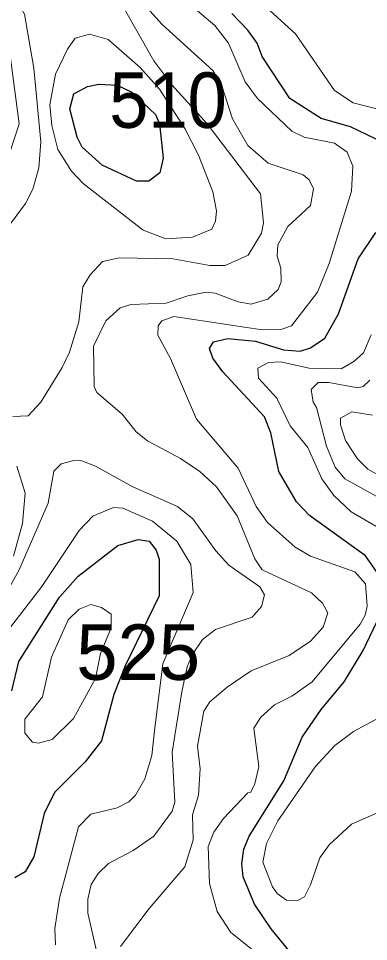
# Model space of a CAD drawing. Extents: x 673.6 to 698.9, y 7012 to 7040.1.
# Drawn here: x 682.378 to 682.883, y 7013.137 to 7014.47 of the extents above; entities that cross this region are included whole.
import ezdxf

# ---------------------------------------------------------------- set-up
doc = ezdxf.new("R2010")
doc.units = 0
doc.header["$LTSCALE"] = 0.032
doc.layers.add('1', color=7, linetype='Continuous', lineweight=25)
doc.layers.add('2', color=7, linetype='Continuous', lineweight=13)
doc.layers.add('21', color=7, linetype='Continuous')

msp = doc.modelspace()

# ---------------------------------------------------------------- linework, layer by layer
at = {"layer": '1'}
for points in [[(682.9054, 7014.29), (682.8574, 7014.3132), (682.8151, 7014.3254), (682.7698, 7014.3541), (682.73, 7014.4147), (682.7227, 7014.434), (682.7095, 7014.4529), (682.6862, 7014.477)], [(682.9052, 7013.6567), (682.8793, 7013.6939), (682.7982, 7013.7522), (682.7797, 7013.7716), (682.7541, 7013.8157), (682.7427, 7013.8711), (682.7335, 7013.8944), (682.6731, 7013.9594), (682.6588, 7013.9792), (682.6539, 7013.993), (682.66, 7014.0028), (682.6803, 7014.0075), (682.7206, 7014.0035), (682.7609, 7013.991), (682.7847, 7013.989), (682.7996, 7013.9942), (682.8203, 7014.0082), (682.8402, 7014.0429), (682.8686, 7014.1225), (682.8938, 7014.1604)], [(682.369, 7013.4986), (682.3791, 7013.5413), (682.4376, 7013.634), (682.4645, 7013.6646), (682.5219, 7013.7085), (682.5509, 7013.7173), (682.567, 7013.715), (682.5772, 7013.7017), (682.5812, 7013.689), (682.5814, 7013.6361), (682.5325, 7013.5348), (682.5162, 7013.4937), (682.4982, 7013.4265), (682.4748, 7013.3965), (682.4305, 7013.3518), (682.4155, 7013.3217), (682.4005, 7013.259), (682.3879, 7013.2373), (682.3733, 7013.2288)], [(682.7989, 7013.0867), (682.7428, 7013.155), (682.7191, 7013.1907), (682.7028, 7013.2302), (682.7006, 7013.2494), (682.7035, 7013.2702), (682.7114, 7013.2889), (682.7613, 7013.369), (682.7879, 7013.4319), (682.8153, 7013.4717), (682.8482, 7013.5119), (682.8759, 7013.5572), (682.9049, 7013.6185)]]:
    msp.add_lwpolyline(points, dxfattribs=at)
msp.add_lwpolyline([(682.5763, 7014.3308), (682.5819, 7014.3175), (682.587, 7014.2677), (682.5825, 7014.2467), (682.5665, 7014.2345), (682.5486, 7014.2349), (682.499, 7014.2576), (682.4705, 7014.2837), (682.4632, 7014.2981), (682.4524, 7014.339), (682.4585, 7014.3609), (682.4782, 7014.3716), (682.4943, 7014.3748), (682.5206, 7014.3733), (682.5419, 7014.3633)], close=True, dxfattribs=at)
at = {"layer": '2'}
for points in [[(682.5678, 7014.5395), (682.6618, 7014.4594), (682.6815, 7014.4341), (682.7056, 7014.378), (682.7232, 7014.3539), (682.773, 7014.3071), (682.7907, 7014.2981), (682.8344, 7014.2894), (682.8525, 7014.2766), (682.8606, 7014.2564), (682.8591, 7014.2203), (682.8265, 7014.1159), (682.8098, 7014.0742), (682.7724, 7014.0256), (682.757, 7014.0207), (682.7298, 7014.0199), (682.6025, 7014.0395), (682.5851, 7014.0332), (682.5799, 7014.0257), (682.5797, 7014.0124), (682.5978, 7013.9787), (682.6351, 7013.891), (682.6953, 7013.8204), (682.7212, 7013.7649), (682.7378, 7013.7417), (682.7774, 7013.7061), (682.7995, 7013.6932), (682.8637, 7013.6708), (682.8789, 7013.6534), (682.8814, 7013.6212), (682.8787, 7013.6083), (682.8712, 7013.5949), (682.802, 7013.5117), (682.7726, 7013.491), (682.7476, 7013.4787), (682.7282, 7013.4606), (682.7179, 7013.4451), (682.725, 7013.3894), (682.7195, 7013.3645), (682.7136, 7013.3525), (682.7095, 7013.3514), (682.674, 7013.3145), (682.6603, 7013.295), (682.6522, 7013.274), (682.6538, 7013.2208), (682.6652, 7013.1801), (682.6847, 7013.1498), (682.735, 7013.1101)], [(682.3636, 7014.1687), (682.3885, 7014.2026), (682.3993, 7014.2232), (682.4078, 7014.2541), (682.4105, 7014.2916), (682.4004, 7014.398), (682.387, 7014.4758), (682.3797, 7014.4884), (682.3387, 7014.5263)], [(682.5209, 7014.5021), (682.5739, 7014.4082), (682.5997, 7014.3739), (682.6506, 7014.3177), (682.7274, 7014.2163), (682.7317, 7014.1744), (682.7292, 7014.1598), (682.7097, 7014.1279), (682.6767, 7014.1128), (682.6546, 7014.1128), (682.6015, 7014.1225), (682.5235, 7014.1242), (682.4998, 7014.1189), (682.482, 7014.0995), (682.4713, 7014.0822), (682.4655, 7014.0317), (682.4518, 7013.9877), (682.4416, 7013.9656), (682.4107, 7013.9158), (682.3923, 7013.896), (682.3703, 7013.895)], [(682.5258, 7013.1296), (682.5671, 7013.1846), (682.6183, 7013.2446), (682.6306, 7013.2835), (682.6296, 7013.32), (682.6381, 7013.3484), (682.6406, 7013.3863), (682.6365, 7013.4187), (682.6458, 7013.4695), (682.6547, 7013.4827), (682.6795, 7013.504), (682.7139, 7013.5275), (682.769, 7013.55), (682.7999, 7013.5704), (682.8182, 7013.5908), (682.8247, 7013.6114), (682.817, 7013.6254), (682.8013, 7013.6404), (682.7298, 7013.6734), (682.7193, 7013.6894), (682.6941, 7013.7516), (682.664, 7013.7933), (682.6399, 7013.8153), (682.6124, 7013.8345), (682.5647, 7013.8596), (682.5483, 7013.873), (682.5279, 7013.8982), (682.4915, 7013.9296), (682.4877, 7013.9381), (682.4868, 7013.9965), (682.5045, 7014.0328), (682.5251, 7014.0517), (682.5404, 7014.0564), (682.5917, 7014.0585), (682.6227, 7014.0692), (682.6493, 7014.0742), (682.6621, 7014.0732), (682.6954, 7014.0605), (682.7142, 7014.0569), (682.7383, 7014.0644), (682.753, 7014.0785), (682.7572, 7014.0893), (682.7571, 7014.1093), (682.7515, 7014.1262), (682.7525, 7014.143), (682.7671, 7014.1694), (682.7997, 7014.1997), (682.804, 7014.2236), (682.7976, 7014.2365), (682.7891, 7014.2439), (682.7385, 7014.2609), (682.7092, 7014.2864), (682.6871, 7014.3245), (682.672, 7014.3725), (682.6586, 7014.3945), (682.5857, 7014.4609), (682.5592, 7014.4904)], [(682.9235, 7014.332), (682.8612, 7014.3476), (682.8345, 7014.3658), (682.778, 7014.4476), (682.7361, 7014.4856)], [(682.3619, 7014.4489), (682.3792, 7014.3173), (682.3665, 7014.2773)], [(682.9089, 7013.7277), (682.8584, 7013.7574), (682.8333, 7013.781), (682.816, 7013.8051), (682.796, 7013.8502), (682.7705, 7013.8815), (682.7512, 7013.9215), (682.7247, 7013.9504), (682.7237, 7013.9649), (682.7391, 7013.973), (682.7563, 7013.9739), (682.7976, 7013.9648), (682.844, 7013.9639), (682.8624, 7013.9745), (682.8761, 7013.9867), (682.8873, 7014.0127)], [(682.8852, 7013.9473), (682.8757, 7013.9384), (682.8678, 7013.9361), (682.8262, 7013.9442), (682.8109, 7013.9442), (682.8008, 7013.934), (682.8034, 7013.9158), (682.8083, 7013.9078), (682.823, 7013.8522), (682.8351, 7013.8216), (682.8491, 7013.8047), (682.9032, 7013.7751)], [(682.9032, 7013.8072), (682.8826, 7013.819), (682.8676, 7013.834), (682.8503, 7013.8601), (682.8428, 7013.8827), (682.8429, 7013.8925), (682.8594, 7013.9015), (682.8892, 7013.8966)], [(682.3384, 7013.6007), (682.379, 7013.6727), (682.421, 7013.7697), (682.4295, 7013.816), (682.4398, 7013.8265), (682.4585, 7013.8316), (682.4696, 7013.8308), (682.4897, 7013.8233), (682.5432, 7013.7932), (682.6079, 7013.7649), (682.6298, 7013.747), (682.6631, 7013.701), (682.6818, 7013.6803), (682.7267, 7013.6492)], [(682.3758, 7013.8234), (682.3881, 7013.784), (682.3841, 7013.7404), (682.3714, 7013.6933)], [(682.5607, 7013.372), (682.5706, 7013.4053), (682.5747, 7013.4412), (682.5867, 7013.538), (682.6306, 7013.6406), (682.6273, 7013.681), (682.6068, 7013.7149), (682.572, 7013.7439), (682.529, 7013.7625), (682.5156, 7013.7635), (682.4856, 7013.7508), (682.466, 7013.7304), (682.412, 7013.6495), (682.3505, 7013.5702)], [(682.7267, 7013.6492), (682.7332, 7013.6373), (682.729, 7013.6205), (682.7154, 7013.6051), (682.6629, 7013.5872), (682.644, 7013.5731)], [(682.644, 7013.5731), (682.629, 7013.551), (682.6217, 7013.5337), (682.6143, 7013.4973), (682.6, 7013.4101), (682.6042, 7013.338), (682.6003, 7013.3249), (682.5735, 7013.2889), (682.5438, 7013.2681), (682.5084, 7013.2493), (682.4933, 7013.2351), (682.4835, 7013.2191), (682.4786, 7013.1981), (682.4785, 7013.178), (682.4962, 7013.1004)], [(682.8949, 7013.3221), (682.8589, 7013.3065), (682.8268, 7013.2766), (682.8133, 7013.2575), (682.7996, 7013.2189), (682.7911, 7013.2014), (682.7811, 7013.1962), (682.7652, 7013.1965), (682.7516, 7013.2063), (682.7447, 7013.2158), (682.731, 7013.2516), (682.7364, 7013.2786), (682.7525, 7013.3113), (682.8064, 7013.3892), (682.835, 7013.4197), (682.8618, 7013.4399), (682.9038, 7013.4629)], [(682.4651, 7013.3024), (682.4826, 7013.3207), (682.5206, 7013.3298), (682.5378, 7013.3386), (682.5473, 7013.3484), (682.5607, 7013.372)], [(682.4319, 7013.132), (682.431, 7013.1557), (682.4375, 7013.1994), (682.4651, 7013.3024)]]:
    msp.add_lwpolyline(points, dxfattribs=at)
for points in [[(682.6589, 7014.2191), (682.6382, 7014.2723), (682.6186, 7014.3109), (682.5821, 7014.3674), (682.554, 7014.3989), (682.5079, 7014.4394), (682.481, 7014.4471), (682.4603, 7014.4411), (682.4489, 7014.4251), (682.4317, 7014.3893), (682.4236, 7014.3447), (682.4266, 7014.3152), (682.4351, 7014.2804), (682.4547, 7014.2491), (682.4715, 7014.2315), (682.5585, 7014.1641), (682.5909, 7014.1514), (682.6294, 7014.1538), (682.6576, 7014.1654), (682.6627, 7014.1768), (682.6643, 7014.1917)], [(682.4966, 7013.5525), (682.4896, 7013.5164), (682.4576, 7013.4588), (682.4272, 7013.4285), (682.4071, 7013.4233), (682.3988, 7013.4245), (682.3875, 7013.4376), (682.3875, 7013.458), (682.4133, 7013.4901), (682.426, 7013.5473), (682.4503, 7013.6013), (682.4661, 7013.6169), (682.4827, 7013.6237), (682.4982, 7013.6193), (682.5123, 7013.6094), (682.5123, 7013.5899)]]:
    msp.add_lwpolyline(points, close=True, dxfattribs=at)

# ---------------------------------------------------------------- texts
at = {"layer": '21', "width": 0.95}
msp.add_text('510', height=0.08, dxfattribs=at).set_placement((682.5094, 7014.3117))
at = {"layer": '21'}
msp.add_text('525', height=0.08, dxfattribs=at).set_placement((682.4619, 7013.5147))

doc.saveas('drawing.dxf')
